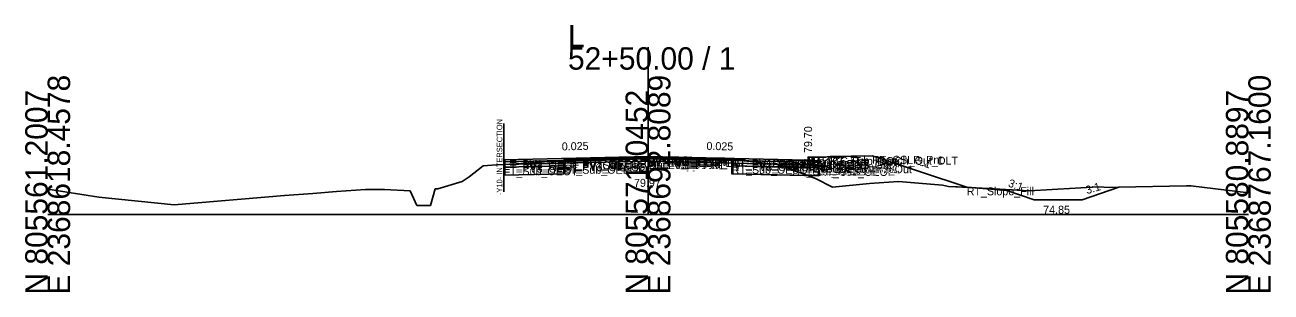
# Model space of a CAD drawing. Extents: x -26 to 8153, y -10 to 9520.
# Drawn here: x 4997.2 to 5152.8, y -9.7 to 23.7 of the extents above; entities that cross this region are included whole.
import ezdxf

# ---------------------------------------------------------------- set-up
doc = ezdxf.new("R2010")
doc.units = 0
for name, color, linetype in [('Exist CMT Pavement', 7, 'Continuous'), ('Exist Cross Section Cell', 7, 'Continuous'), ('Exist XS Center Line Elevation Label', 7, 'Continuous'), ('Exist XS Ground Line', 7, 'Continuous'), ('Prop CMT Conc Surface', 7, 'Continuous'), ('Prop CMT Concrete Structures', 7, 'Continuous'), ('Prop CMT Ditch DDE', 7, 'Continuous'), ('Prop CMT Pvmt Course 1', 7, 'Continuous'), ('Prop CMT Pvmt Course 1 CG', 7, 'Continuous'), ('Prop CMT Pvmt Course 1 Wedge', 7, 'Continuous'), ('Prop CMT Pvmt Course 2', 7, 'Continuous'), ('Prop CMT Pvmt Course 2 Wedge', 7, 'Continuous'), ('Prop CMT Pvmt Course 3', 7, 'Continuous'), ('Prop CMT Pvmt Course 3 Wedge', 7, 'Continuous'), ('Prop CMT Pvmt Surface', 7, 'Continuous'), ('Prop CMT Pvmt Wedge Surface 1', 7, 'Continuous'), ('Prop CMT Pvmt Wedge Surface 2', 7, 'Continuous'), ('Prop CMT Pvmt Wedge Surface 3', 7, 'Continuous'), ('Prop CMT Shallow Undercut', 7, 'Continuous'), ('Prop CMT Shallow Undercut Boundary', 7, 'Continuous'), ('Prop CMT Shear Line', 7, 'Continuous'), ('Prop CMT Slope Grass', 7, 'Continuous'), ('Prop CMT Subgrade Earthwork', 7, 'Continuous'), ('Prop XS Earthwork Shape', 7, 'Continuous'), ('Prop XS Hydro Elevations', 7, 'Continuous'), ('Prop XS SE Text', 7, 'Continuous'), ('Prop XS Side Slope Text', 7, 'Continuous'), ('Prop XS Subgrade Earthwork', 7, 'Continuous'), ('Scratch_Level_2', 7, 'Continuous'), ('Scratch_Level_6', 7, 'Continuous')]:
    doc.layers.add(name, color=color, linetype=linetype)

msp = doc.modelspace()

# ---------------------------------------------------------------- linework, layer by layer
at = {"layer": 'Exist CMT Pavement'}
for p, q in [((5062.66, 6.66), (5065.96, 6.7)), ((5065.96, 6.7), (5074.91, 6.98)), ((5074.91, 6.98), (5076.85, 6.97)), ((5076.85, 6.97), (5085.45, 6.9))]:
    msp.add_line(p, q, dxfattribs=at)
at = {"layer": 'Exist Cross Section Cell'}
for p, q in [((5075, 0), (5075, 20.93)), ((5000, 0), (5075, 0)), ((5075, 0), (5150, 0))]:
    msp.add_line(p, q, dxfattribs=at)
at = {"layer": 'Exist XS Ground Line'}
for p, q in [((5055.47, 6.19), (5056.06, 6.23)), ((5056.06, 6.23), (5058.52, 6.33)), ((5058.52, 6.33), (5062.66, 6.66)), ((5062.66, 6.66), (5065.96, 6.7)), ((5065.96, 6.7), (5074.91, 6.98)), ((5074.91, 6.98), (5076.85, 6.97)), ((5076.85, 6.97), (5085.45, 6.9)), ((5085.45, 6.9), (5087.01, 6.73)), ((5087.01, 6.73), (5091.47, 6.22)), ((5051.77, 4.12), (5052.67, 4.72)), ((5052.67, 4.72), (5054.41, 6.1)), ((5054.41, 6.1), (5055.47, 6.19)), ((5091.47, 6.22), (5095.91, 4.5)), ((5000, 3.19), (5006.4, 2.16)), ((5036.07, 2.88), (5039.69, 3.14)), ((5039.69, 3.14), (5042.09, 3.13)), ((5042.09, 3.13), (5045.27, 2.99)), ((5047.81, 1.13), (5048.4, 3.23)), ((5048.4, 3.23), (5048.74, 3.24)), ((5048.74, 3.24), (5051.77, 4.12)), ((5095.91, 4.5), (5098.04, 3.42)), ((5098.04, 3.42), (5102.66, 3.9)), ((5102.66, 3.9), (5106.29, 4.16)), ((5106.29, 4.16), (5111.79, 3.67)), ((5111.79, 3.67), (5112.54, 3.53)), ((5112.54, 3.53), (5116.01, 3.36)), ((5116.01, 3.36), (5122.62, 2.98)), ((5122.62, 2.98), (5131.25, 3.46)), ((5131.25, 3.46), (5132.71, 3.4)), ((5132.71, 3.4), (5133.83, 3.42)), ((5133.83, 3.42), (5142.28, 3.61)), ((5142.28, 3.61), (5142.8, 3.61)), ((5142.8, 3.61), (5150, 2.74)), ((5006.4, 2.16), (5015.79, 1.22)), ((5015.79, 1.22), (5029.57, 2.39)), ((5029.57, 2.39), (5033.13, 2.66)), ((5033.13, 2.66), (5036.07, 2.88)), ((5045.27, 2.99), (5046.13, 1.13)), ((5046.13, 1.13), (5047.27, 1.13)), ((5047.27, 1.13), (5047.81, 1.13))]:
    msp.add_line(p, q, dxfattribs=at)
at = {"layer": 'Prop CMT Conc Surface'}
for points in [[(5093, 6.83), (5095, 6.7)], [(5095, 6.7), (5095, 7.2), (5095.5, 7.2)]]:
    msp.add_lwpolyline(points, dxfattribs=at)
at = {"layer": 'Prop CMT Concrete Structures'}
for points in [[(5093, 6.83), (5095, 6.7), (5095, 7.2), (5095.5, 7.2)], [(5095.5, 7.2), (5095.5, 6.19), (5093, 6.25)], [(5093, 6.25), (5093, 6.83)]]:
    msp.add_lwpolyline(points, dxfattribs=at)
at = {"layer": 'Prop CMT Ditch DDE'}
for p, q in [((5119.81, 3), (5114.81, 3.42)), ((5133.83, 3.42), (5129.25, 1.85)), ((5123.25, 1.85), (5119.81, 3)), ((5123.25, 1.85), (5129.25, 1.85))]:
    msp.add_line(p, q, dxfattribs=at)
at = {"layer": 'Prop CMT Pvmt Course 1'}
for points in [[(5075, 7.28), (5057, 6.83)], [(5057, 6.83), (5057, 6.58)], [(5057, 6.58), (5064.48, 6.77)], [(5064.48, 6.9), (5075, 7.16)], [(5064.48, 6.77), (5064.48, 6.9)], [(5075, 7.03), (5075, 7.28)], [(5075, 7.28), (5093, 6.83)], [(5075, 7.03), (5075, 7.28)], [(5075, 7.16), (5075, 7.03), (5075, 7.03)], [(5085.46, 6.9), (5075, 7.16)], [(5075, 7.16), (5075, 7.03), (5075, 7.03)], [(5085.46, 6.77), (5085.46, 6.9)], [(5093, 6.58), (5085.46, 6.77)], [(5093, 6.83), (5093, 6.58)]]:
    msp.add_lwpolyline(points, dxfattribs=at)
at = {"layer": 'Prop CMT Pvmt Course 1 CG'}
for points in [[(5093, 6.25), (5096, 6.18), (5096.34, 5.84)], [(5093, 5.92), (5093, 6.25)], [(5096.34, 5.84), (5093, 5.92)]]:
    msp.add_lwpolyline(points, dxfattribs=at)
at = {"layer": 'Prop CMT Pvmt Course 1 Wedge'}
for points in [[(5075, 7.16), (5064.48, 6.9)], [(5075, 7.16), (5085.46, 6.9)]]:
    msp.add_lwpolyline(points, dxfattribs=at)
at = {"layer": 'Prop CMT Pvmt Course 2'}
for points in [[(5064.48, 6.77), (5057, 6.58)], [(5057, 6.58), (5057, 6.25)], [(5057, 6.25), (5064.48, 6.44)], [(5064.48, 6.44), (5064.48, 6.77)], [(5085.46, 6.44), (5085.46, 6.77)], [(5085.46, 6.77), (5093, 6.58)], [(5093, 6.25), (5085.46, 6.44)], [(5093, 6.58), (5093, 6.25)]]:
    msp.add_lwpolyline(points, dxfattribs=at)
at = {"layer": 'Prop CMT Pvmt Course 2 Wedge'}
for points in [[(5075, 7.03), (5064.48, 6.77)], [(5075, 7.03), (5085.46, 6.77)]]:
    msp.add_lwpolyline(points, dxfattribs=at)
at = {"layer": 'Prop CMT Pvmt Course 3'}
for points in [[(5064.48, 6.44), (5057, 6.25)], [(5057, 6.25), (5057, 5.92)], [(5064.48, 6.11), (5064.48, 6.44)], [(5085.46, 6.44), (5093, 6.25)], [(5085.46, 6.11), (5085.46, 6.44)], [(5093, 6.25), (5093, 5.92)], [(5057, 5.92), (5064.48, 6.11)], [(5093, 5.92), (5085.46, 6.11)]]:
    msp.add_lwpolyline(points, dxfattribs=at)
at = {"layer": 'Prop CMT Pvmt Course 3 Wedge'}
for points in [[(5075, 6.7), (5064.48, 6.44)], [(5075, 6.7), (5085.46, 6.44)]]:
    msp.add_lwpolyline(points, dxfattribs=at)
at = {"layer": 'Prop CMT Pvmt Surface'}
for points in [[(5075, 7.28), (5057, 6.83), (5057, 6.27)], [(5075, 7.28), (5093, 6.83)]]:
    msp.add_lwpolyline(points, dxfattribs=at)
at = {"layer": 'Prop CMT Pvmt Wedge Surface 1'}
for points in [[(5057, 6.58), (5057, 6.83)], [(5064.48, 6.77), (5057, 6.58)], [(5075, 7.16), (5064.48, 6.9)], [(5064.48, 6.9), (5064.48, 6.77)], [(5075, 7.16), (5085.46, 6.9)], [(5085.46, 6.9), (5085.46, 6.77)], [(5085.46, 6.77), (5093, 6.58)], [(5093, 6.58), (5093, 6.83)]]:
    msp.add_lwpolyline(points, dxfattribs=at)
at = {"layer": 'Prop CMT Pvmt Wedge Surface 2'}
for points in [[(5075, 7.03), (5057, 6.58)], [(5057, 6.58), (5057, 6.83)], [(5075, 7.03), (5093, 6.58)], [(5093, 6.58), (5093, 6.83)]]:
    msp.add_lwpolyline(points, dxfattribs=at)
at = {"layer": 'Prop CMT Pvmt Wedge Surface 3'}
for points in [[(5057, 6.25), (5057, 6.83)], [(5075, 6.7), (5057, 6.25)], [(5075, 6.7), (5093, 6.25)], [(5093, 6.25), (5093, 6.83)]]:
    msp.add_lwpolyline(points, dxfattribs=at)
at = {"layer": 'Prop CMT Shallow Undercut'}
for p, q in [((5064.48, 6.11), (5057, 5.92)), ((5057, 5.92), (5057, 4.92)), ((5057, 4.92), (5064.48, 5.11)), ((5064.48, 5.11), (5064.48, 6.11))]:
    msp.add_line(p, q, dxfattribs=at)
msp.add_lwpolyline([(5094.94, 4.87), (5085.46, 5.11), (5085.46, 6.11), (5092.18, 5.94)], close=True, dxfattribs=at)
at = {"layer": 'Prop CMT Shallow Undercut Boundary'}
for p, q in [((5057, 5.92), (5057, 4.92)), ((5057, 4.92), (5064.48, 5.11)), ((5064.48, 6.11), (5064.48, 5.11)), ((5085.46, 6.11), (5085.46, 5.11)), ((5096.34, 4.84), (5085.46, 5.11)), ((5096.34, 5.84), (5096.34, 4.84))]:
    msp.add_line(p, q, dxfattribs=at)
at = {"layer": 'Prop CMT Shear Line'}
msp.add_line((5057, 2.84), (5057, 11.41), dxfattribs=at)
at = {"layer": 'Prop CMT Slope Grass'}
msp.add_lwpolyline([(5095.5, 7.2), (5103, 7.35), (5114.81, 3.42)], dxfattribs=at)
at = {"layer": 'Prop CMT Subgrade Earthwork'}
for points in [[(5064.48, 6.11), (5064.48, 6.68)], [(5085.46, 6.11), (5085.44, 6.9)], [(5093, 5.92), (5096.34, 5.84), (5097.75, 7.25)], [(5064.48, 6.11), (5057, 5.92)], [(5085.46, 6.11), (5093, 5.92)]]:
    msp.add_lwpolyline(points, dxfattribs=at)
at = {"layer": 'Prop XS Earthwork Shape'}
for p, q in [((5116.01, 3.36), (5114.81, 3.42)), ((5114.81, 3.42), (5119.81, 3)), ((5122.62, 2.98), (5116.01, 3.36)), ((5131.25, 3.46), (5122.62, 2.98)), ((5129.25, 1.85), (5133.83, 3.42)), ((5132.71, 3.4), (5131.25, 3.46)), ((5133.83, 3.42), (5132.71, 3.4)), ((5119.81, 3), (5123.25, 1.85)), ((5123.25, 1.85), (5129.25, 1.85))]:
    msp.add_line(p, q, dxfattribs=at)
for points in [[(5085.44, 6.9), (5085.45, 6.9), (5087.01, 6.73), (5091.47, 6.22), (5092.18, 5.94), (5085.46, 6.11)], [(5098.04, 3.42), (5102.66, 3.9), (5106.29, 4.16), (5111.79, 3.67), (5112.54, 3.53), (5114.81, 3.42), (5103, 7.35), (5097.75, 7.25), (5096.34, 5.84), (5096.34, 4.84), (5094.94, 4.87), (5095.91, 4.5)], [(5057, 4.92), (5064.48, 5.11), (5064.48, 6.11), (5057, 5.92)], [(5085.46, 6.11), (5092.18, 5.94), (5094.94, 4.87), (5085.46, 5.11)], [(5096.34, 4.84), (5094.94, 4.87), (5092.18, 5.94), (5093, 5.92), (5096.34, 5.84)]]:
    msp.add_lwpolyline(points, close=True, dxfattribs=at)
at = {"layer": 'Prop XS Subgrade Earthwork'}
for p, q in [((5057, 5.92), (5064.48, 6.11)), ((5085.46, 6.11), (5096.34, 5.84))]:
    msp.add_line(p, q, dxfattribs=at)
at = {"layer": 'Scratch_Level_6'}
for p, q in [((5064.48, 6.11), (5057, 5.92)), ((5057, 5.92), (5057, 4.92)), ((5057, 4.92), (5064.48, 5.11)), ((5064.48, 5.11), (5064.48, 6.11))]:
    msp.add_line(p, q, dxfattribs=at)
msp.add_lwpolyline([(5094.94, 4.87), (5085.46, 5.11), (5085.46, 6.11), (5092.18, 5.94)], close=True, dxfattribs=at)

# ---------------------------------------------------------------- texts
at = {"layer": 'Exist Cross Section Cell'}
for s, p in [('L', (5065, 20.93)), ('52+50.00 / 1', (5065, 18.13))]:
    msp.add_text(s, height=2.8, dxfattribs=at).set_placement(p)
for s, p in [('E 2368618.4578', (5002.8, -10)), ('E 2368692.8089', (5077.8, -10)), ('E 2368767.1600', (5152.8, -10)), ('N 805561.2007', (5000, -10)), ('N 805571.0452', (5075, -10)), ('N 805580.8897', (5150, -10))]:
    msp.add_text(s, height=2.8, rotation=90, dxfattribs=at).set_placement(p)
at = {"layer": 'Exist XS Center Line Elevation Label'}
msp.add_text('79.97', height=1, dxfattribs=at).set_placement((5073.25, 3.47))
at = {"layer": 'Prop CMT Shear Line'}
msp.add_text('-Y10- INTERSECTION', height=0.7, rotation=90, dxfattribs=at).set_placement((5056.8, 2.44))
at = {"layer": 'Prop XS Hydro Elevations'}
msp.add_text('79.70', height=1, rotation=90, dxfattribs=at).set_placement((5095.5, 7.7))
at = {"layer": 'Prop XS SE Text'}
for rotation, p in [(1.4321, (5064.24, 8.02)), (358.5679, (5082.29, 8.1))]:
    msp.add_text('0.025', height=1, rotation=rotation, dxfattribs=at).set_placement(p)
at = {"layer": 'Prop XS Side Slope Text'}
for rotation, p in [(341.5651, (5108.39, 6.35)), (340.5375, (5119.91, 3.54)), (16.5748, (5129.84, 2.55))]:
    msp.add_text('3:1', height=1, rotation=rotation, dxfattribs=at).set_placement(p)
msp.add_text('74.85', height=1, dxfattribs=at).set_placement((5124.37, 0.11))
at = {"layer": 'Scratch_Level_2'}
for s, p in [('LT_PV1_OEOT', (5057, 5.83)), ('LT_PV2_OEOT', (5057, 5.58)), ('LT_PV3_OEOT', (5057, 5.25)), ('LT_PV1_OEEOP', (5064.48, 5.9)), ('LT_PV2_OEEOP', (5064.48, 5.77)), ('LT_PV_OEEOP_EG', (5064.48, 5.68)), ('LT_PV3_OEEOP', (5064.48, 5.44)), ('LT_PV_Sub_Tie_Out', (5064.49, 5.68)), ('PV1_PGL', (5075, 6.28)), ('RT_PV1_IEEOP', (5075, 6.16)), ('LT_PV1_IEEOP', (5075, 6.16)), ('RT_PV2_IEEOP', (5075, 6.03)), ('LT_PV2_IEEOP', (5075, 6.03)), ('PV2_PGL', (5075, 6.03)), ('RT_PV_IEEOP_EG', (5075, 5.97)), ('LT_PV_IEEOP_EG', (5075, 5.97)), ('RT_PV3_IEEOP', (5075, 5.7)), ('LT_PV3_IEEOP', (5075, 5.7)), ('RT_PV_Sub_Tie_Out', (5085.44, 5.9)), ('RT_PV_OEEOP_EG', (5085.46, 5.9)), ('RT_PV1_OEEOP', (5085.46, 5.9)), ('RT_PV2_OEEOP', (5085.46, 5.77)), ('RT_PV3_OEEOP', (5085.46, 5.44)), ('RT_PV1_OEOT', (5093, 5.83)), ('RT_PV2_OEOT', (5093, 5.58)), ('RT_PV3_OEOT', (5093, 5.25)), ('RT_CG_Bot_IE', (5093, 5.25)), ('RT_CG_Top_Face', (5095, 6.2)), ('RT_CG_Top_Gut', (5095, 5.7)), ('RT_CG_Top_BOC', (5095.5, 6.2)), ('RT_CG1_Shelf_Out', (5096, 5.18)), ('RT_Sub_Trench_Out_DLT', (5097.75, 6.25)), ('RT_CSLP_Pnt', (5103, 6.35)), ('LT_Sub_OEOT', (5057, 4.92)), ('LT_Sub_OEEOP', (5064.48, 5.11)), ('RT_Sub_OEEOP', (5085.46, 5.11)), ('RT_Sub_OEOT', (5093, 4.92)), ('RT_CG_Bot_BOC', (5095.5, 5.19)), ('RT_Sub_OEOP', (5096.34, 4.84)), ('RT_Slope_Fill', (5114.81, 2.42))]:
    msp.add_text(s, height=1, dxfattribs=at).set_placement(p)

doc.saveas('drawing.dxf')
